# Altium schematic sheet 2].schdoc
size 368 x 260 mm
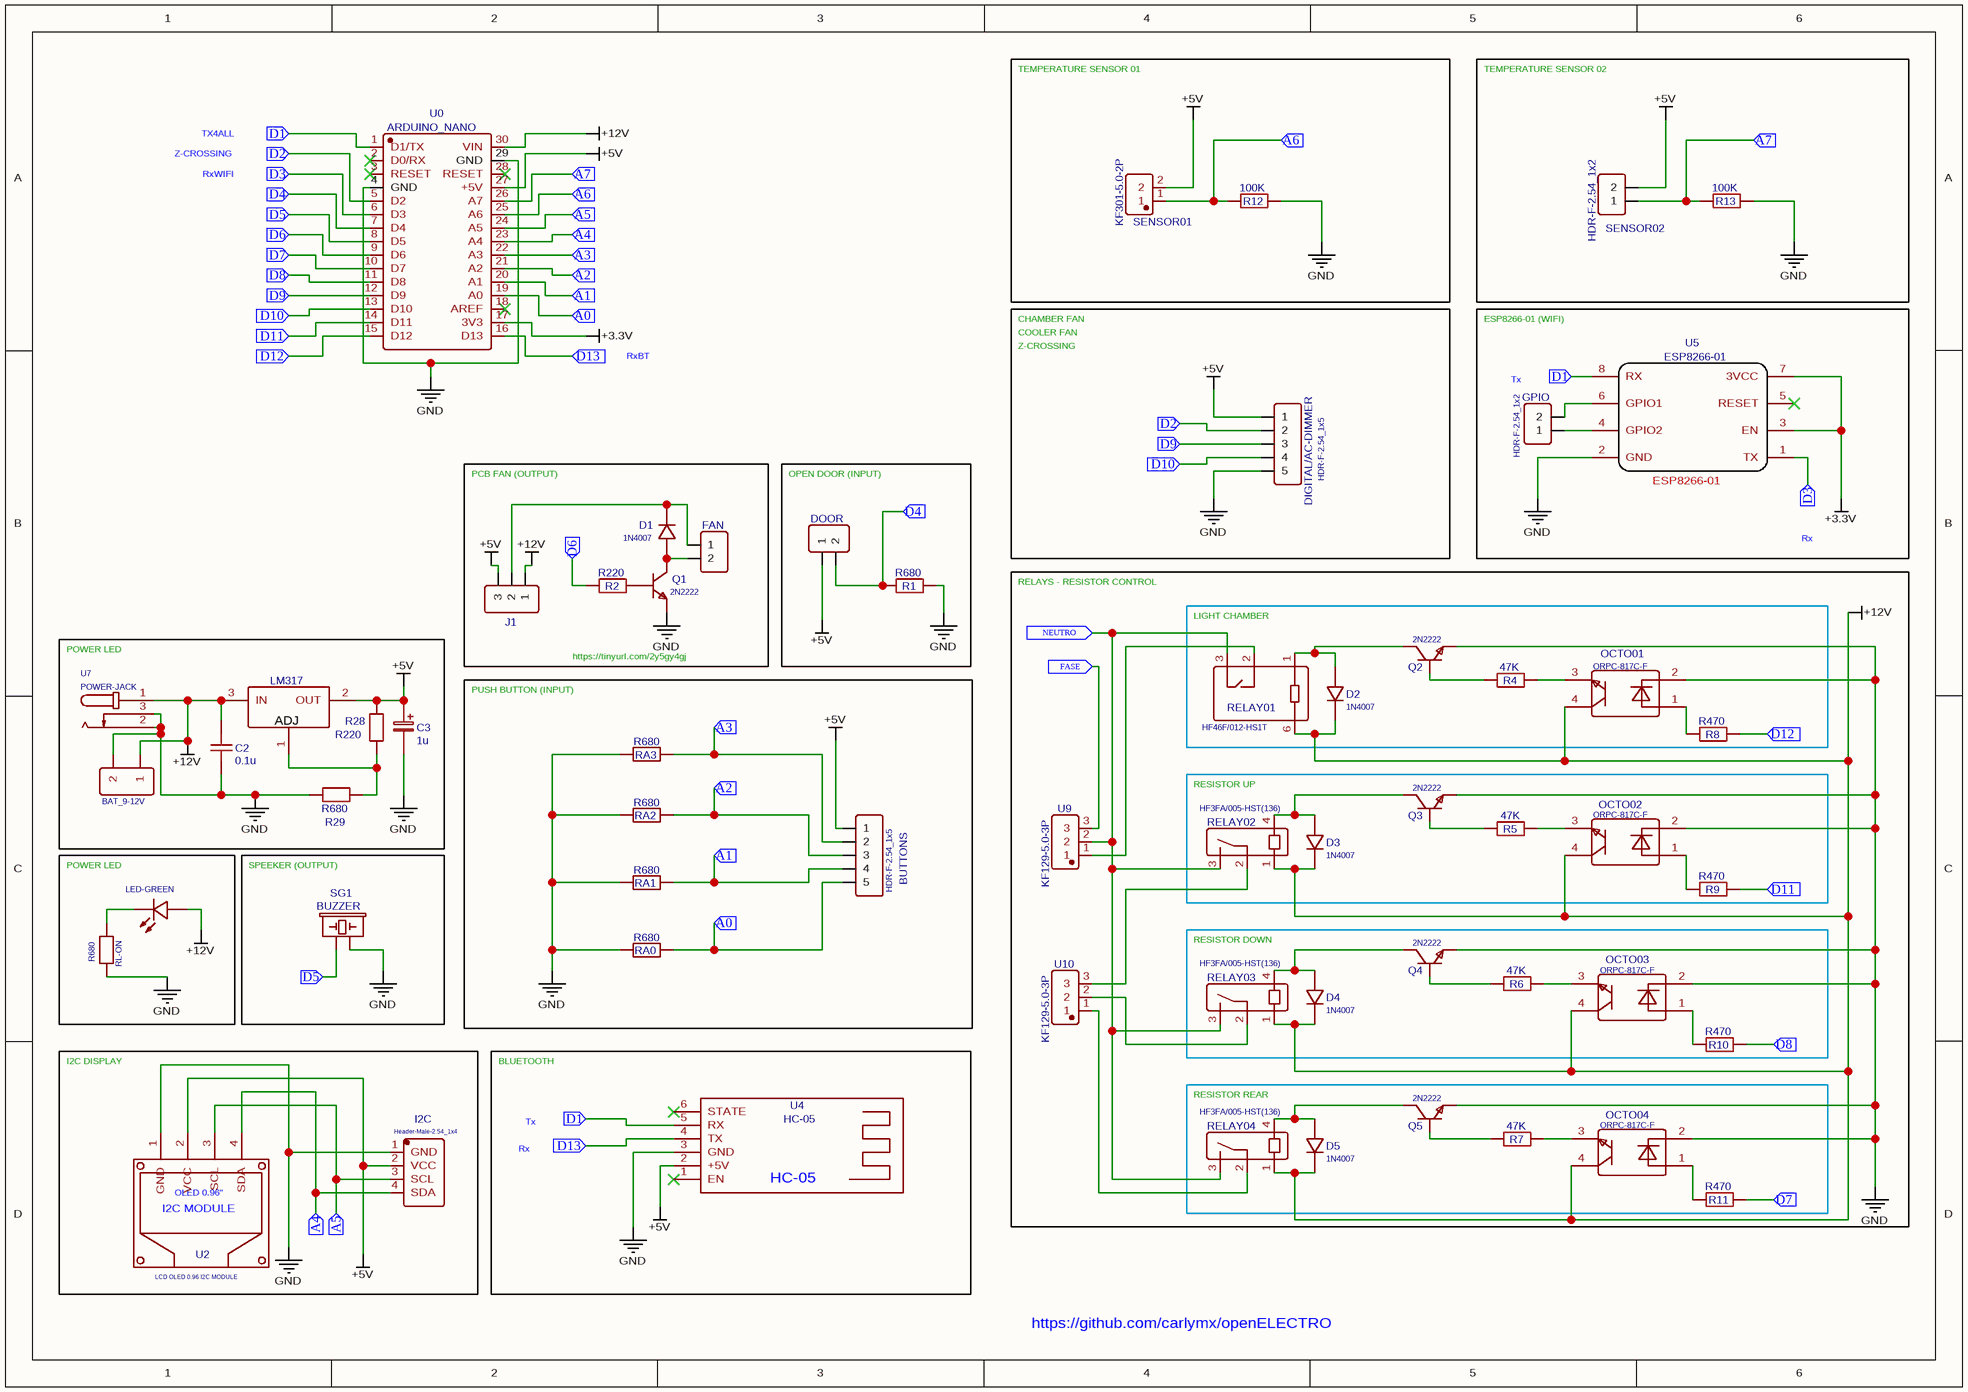
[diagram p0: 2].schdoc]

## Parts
BAT_9-12V  Header-Male-2.54_1x2  [HDR-2X1/2.54]  (value not drawn)
BUTTONS  HDR-F-2.54_1x5  [HDR-F-2.54_1X5]
C2  0.1u  [RAD-0.1]
C3  1u  [CAP-D5.0-F2.0]
D1  1N4007  [DO-41_BD2.4-L4.7-P8.70-D0.6-RD]
D2  1N4007  [DO-41_BD2.4-L4.7-P8.70-D0.9-RD]
D3  1N4007  [DO-41_BD2.4-L4.7-P8.70-D0.9-RD]
D4  1N4007  [DO-41_BD2.4-L4.7-P8.70-D0.9-RD]
D5  1N4007  [DO-41_BD2.4-L4.7-P8.70-D0.9-RD]
DIGITAL/AC-DIMMER  HDR-F-2.54_1x5  [HDR-F-2.54_1X5]
DOOR  HDR-F-2.54_1x2  [HDR-F-2.54_1X2]  (value not drawn)
FAN  HDR-F-2.54_1x2  [HDR-F-2.54_1X2]  (value not drawn)
GPIO  HDR-F-2.54_1x2  [HDR-F-2.54_1X2]
I2C  Header-Male-2.54_1x4  [DIP-1X4P-2.54MM-M]
J1  HDR-F-2.54_1x3  [HDR-F-2.54_1X3]  (value not drawn)
LED-GREEN  204-10SURD/S530-A3  [LED-3MM/2.54]  (value not drawn)
LM317  LM317LZ  [TO-92-3_L4.9-W3.7-P1.27-L]  (value not drawn)
OCTO01  ORPC-817C-F  [DIP-4_L4.6-W6.5-P2.54-LS7.6-BR]
OCTO02  ORPC-817C-F  [DIP-4_L4.6-W6.5-P2.54-LS7.6-BR]
OCTO03  ORPC-817C-F  [DIP-4_L4.6-W6.5-P2.54-LS7.6-BR]
OCTO04  ORPC-817C-F  [DIP-4_L4.6-W6.5-P2.54-LS7.6-BR]
Q1  2N2222  [TO-92-3_L4.9-W3.7-P1.27-L]
Q2  2N2222  [TO-92-3_L4.9-W3.7-P1.27-L]
Q3  2N2222  [TO-92-3_L4.9-W3.7-P1.27-L]
Q4  2N2222  [TO-92-3_L4.9-W3.7-P1.27-L]
Q5  2N2222  [TO-92-3_L4.9-W3.7-P1.27-L]
R1  R680  [R_AXIAL-0.3]
R2  R220  [R_AXIAL-0.3]
R4  47K  [R_AXIAL-0.3]
R5  47K  [R_AXIAL-0.3]
R6  47K  [R_AXIAL-0.3]
R7  47K  [R_AXIAL-0.3]
R8  R470  [R_AXIAL-0.3]
R9  R470  [R_AXIAL-0.3]
R10  R470  [R_AXIAL-0.3]
R11  R470  [R_AXIAL-0.3]
R12  100K  [R_AXIAL-0.3]
R13  100K  [R_AXIAL-0.3]
R28  R220  [R_AXIAL-0.3]
R29  R680  [R_AXIAL-0.3]
RA0  R680  [R_AXIAL-0.3]
RA1  R680  [R_AXIAL-0.3]
RA2  R680  [R_AXIAL-0.3]
RA3  R680  [R_AXIAL-0.3]
RELAY01  HF46F/012-HS1T  [RELAYS-TH_HF46F-XX-HS1-XXX]
RELAY02  HF3FA/005-HST(136)  [RELAY-TH_HF3FA-005-HST-136]
RELAY03  HF3FA/005-HST(136)  [RELAY-TH_HF3FA-005-HST-136]
RELAY04  HF3FA/005-HST(136)  [RELAY-TH_HF3FA-005-HST-136]
RL-ON  R680  [AXIAL-0.3]
SENSOR01  KF301-5.0-2P  [CONN-TH_P5.00_KF301-5.0-2P]
SENSOR02  HDR-F-2.54_1x2  [HDR-F-2.54_1X2]
SG1  BUZZER  [BUZZER-12MM-NS-KIT]
U0  ARDUINO_NANO  [COMM-TH_ARDUINO_NANO]
U2  LCD OLED 0.96 I2C MODULE  [HDR-F-2.54_1X4]
U4  HC-05  [HDR-F-2.54_1X6]
U5  ESP8266-01  [HDR-F-2.54_2X4]
U7  POWER-JACK  [DC-IN-TH_POWER-JACK]
U9  KF129-5.0-3P  [CONN-TH_3P-P5.00_KF129-5.0-3P]
U10  KF129-5.0-3P  [CONN-TH_3P-P5.00_KF129-5.0-3P]

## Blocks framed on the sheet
TEMPERATURE SENSOR 01: R12 SENSOR01
TEMPERATURE SENSOR 02: R13 SENSOR02
OPEN DOOR (INPUT): DOOR R1
RELAYS - RESISTOR CONTROL: U9 U10
POWER LED: BAT_9-12V C2 C3 LM317 R28 R29 U7
LIGHT CHAMBER: D2 OCTO01 Q2 R4 R8 RELAY01
RESISTOR UP: D3 OCTO02 Q3 R5 R9 RELAY02
POWER LED: LED-GREEN RL-ON
SPEEKER (OUTPUT): SG1
RESISTOR DOWN: D4 OCTO03 Q4 R6 R10 RELAY03
I2C DISPLAY: I2C U2
RESISTOR REAR: D5 OCTO04 Q5 R7 R11 RELAY04

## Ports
A0 (in), A1 (in), A2 (in), A3 (in), A4 (in), A5 (in), A6 (in), A7 (in), D1 (in), D2 (in), D3 (in), D4 (in), D5 (in), D6 (in), D7 (in), D8 (in), D9 (in), D10 (in), D11 (in), D12 (in), D13 (in), FASE (in), NEUTRO (in)

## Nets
+3.3V: U0.17(3V3) U5.3(EN) U5.7(3VCC)
+5V: BUTTONS.1 C3.1 DIGITAL/AC-DIMMER.1 DOOR.1 I2C.2(VCC) J1.3 LM317.2(OUT) R28.2 SENSOR01.2 SENSOR02.2 U0.27(+5V) U2.2(VCC) U4.2(+5V)
+12V: BAT_9-12V.1 C2.2 D2.1 D3.1 D4.1 D5.1 J1.1 LED-GREEN.1(A) LM317.3(IN) OCTO01.4 OCTO02.4 OCTO03.4 OCTO04.4 RELAY01.6 RELAY02.1 RELAY03.1 RELAY04.1 U0.30(VIN) U7.1
GND: BAT_9-12V.2 C2.1 C3.2 DIGITAL/AC-DIMMER.5 I2C.1(GND) OCTO01.2 OCTO02.2 OCTO03.2 OCTO04.2 Q1.1(E) Q2.1(E) Q3.1(E) Q4.1(E) Q5.1(E) R1.1 R12.2 R13.2 R29.1 RA0.1 RA1.1 RA2.1 RA3.1 RL-ON.1 SG1.- U0.4(GND) U0.29(GND) U2.1(GND) U4.3(GND) U5.2(GND) U7.2 U7.3
A0: BUTTONS.5 RA0.2 U0.19(A0) ; port A0
A1: BUTTONS.4 RA1.2 U0.20(A1) ; port A1
A2: BUTTONS.3 RA2.2 U0.21(A2) ; port A2
A3: BUTTONS.2 RA3.2 U0.22(A3) ; port A3
A4: I2C.4(SDA) U0.23(A4) U2.4(SDA) ; port A4
A5: I2C.3(SCL) U0.24(A5) U2.3(SCL) ; port A5
A6: R12.1 SENSOR01.1 U0.25(A6) ; port A6
A7: R13.1 SENSOR02.1 U0.26(A7) ; port A7
D1: U0.1(D1/TX) U4.5(RX) U5.8(RX) ; port D1
D2: DIGITAL/AC-DIMMER.2 U0.5(D2) ; port D2
D3: U0.6(D3) U5.1(TX) ; port D3
D4: DOOR.2 R1.2 U0.7(D4) ; port D4
D5: SG1.+ U0.8(D5) ; port D5
D6: R2.1 U0.9(D6) ; port D6
D7: R11.2 U0.10(D7) ; port D7
D8: R10.2 U0.11(D8) ; port D8
D9: DIGITAL/AC-DIMMER.3 U0.12(D9) ; port D9
D10: DIGITAL/AC-DIMMER.4 U0.13(D10) ; port D10
D11: R9.2 U0.14(D11) ; port D11
D12: R8.2 U0.15(D12) ; port D12
D13: U0.16(D13) U4.4(TX) ; port D13
FASE: U9.3 ; port FASE
NEUTRO: RELAY01.3 RELAY02.3 RELAY03.3 RELAY04.3 U9.2 ; port NEUTRO
NetD1_1: D1.1 FAN.1 J1.2
NetD1_2: D1.2 FAN.2 Q1.3(C)
NetD2_2: D2.2 Q2.3(C) RELAY01.1
NetD3_2: D3.2 Q3.3(C) RELAY02.4
NetD4_2: D4.2 Q4.3(C) RELAY03.4
NetD5_2: D5.2 Q5.3(C) RELAY04.4
NetGPIO_1: GPIO.1 U5.4(GPIO2)
NetGPIO_2: GPIO.2 U5.6(GPIO1)
NetLED-GREEN_2: LED-GREEN.2(K) RL-ON.2
NetLM317_1: LM317.1(ADJ) R28.1 R29.2
NetOCTO01_1: OCTO01.1 R8.1
NetOCTO01_3: OCTO01.3 R4.1
NetOCTO02_1: OCTO02.1 R9.1
NetOCTO02_3: OCTO02.3 R5.2
NetOCTO03_1: OCTO03.1 R10.1
NetOCTO03_3: OCTO03.3 R6.2
NetOCTO04_1: OCTO04.1 R11.1
NetOCTO04_3: OCTO04.3 R7.2
NetQ1_2: Q1.2(B) R2.2
NetQ2_2: Q2.2(B) R4.2
NetQ3_2: Q3.2(B) R5.1
NetQ4_2: Q4.2(B) R6.1
NetQ5_2: Q5.2(B) R7.1
NetRELAY01_2: RELAY01.2 U9.1
NetRELAY02_2: RELAY02.2 U10.3
NetRELAY03_2: RELAY03.2 U10.2
NetRELAY04_2: RELAY04.2 U10.1

Not connected (* = marked no-connect by the designer): U0 2(D0/RX)* 3(RESET)* 18(AREF)* 28(RESET)*; U4 1(EN)* 6(STATE)*; U5 5(RESET)*

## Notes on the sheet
- Z-CROSSING
- TX4ALL
- RxWIFI
- COOLER FAN
- CHAMBER FAN
- ESP8266-01 (WIFI)
- RxBT
- (near GPIO) Tx
- PCB FAN (OUTPUT)
- Rx
- https://tinyurl.com/2y5gy4gj
- PUSH BUTTON (INPUT)
- BLUETOOTH
- Tx
- https://github.com/carlymx/openELECTRO

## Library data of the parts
BAT_9-12V = Header-Male-2.54_1x2: BOM_Manufacturer: TE Connectivity; BOM_Manufacturer Part: 826629-2
BUTTONS DIGITAL/AC-DIMMER = HDR-F-2.54_1x5: Contributor: LCEDA_Lib
C2 = 0.1u: nameAlias: Value(F); Contributor: LCEDA_Lib
C3 = 1u: nameAlias: Value(F); Contributor: LCEDA_Lib
D1-D5 = 1N4007: BOM_Manufacturer: SEMTECH; Contributor: LCEDA_Lib
DOOR FAN GPIO SENSOR02 = HDR-F-2.54_1x2: Contributor: LCEDA_Lib
I2C = Header-Male-2.54_1x4: BOM_Manufacturer: Ckmtw; BOM_Manufacturer Part: 210S-1*4P L=11.6MMGold-plated black; Contributor: LCSC
J1 = HDR-F-2.54_1x3: Contributor: LCEDA_Lib
LED-GREEN = 204-10SURD/S530-A3: BOM_Manufacturer: EVERLIGHT
LM317 = LM317LZ: BOM_Manufacturer: ON Semiconductor; BOM_Manufacturer Part: LM317LZG; Contributor: LCSC
OCTO01 OCTO02 OCTO03 OCTO04 = ORPC-817C-F: BOM_Manufacturer: Orient(奥伦德); Contributor: LCSC
Q1-Q5 = 2N2222: BOM_Manufacturer: SEMTECH; Contributor: LCSC
R1 R29 = R680: nameAlias: Value(Ω); Contributor: LCEDA_Lib
R2 R28 = R220: nameAlias: Value(Ω); Contributor: LCEDA_Lib
R4-R7 = 47K: nameAlias: Value(Ω); Contributor: LCEDA_Lib
R8-R11 = R470: nameAlias: Value(Ω); Contributor: LCEDA_Lib
R12 R13 = 100K: nameAlias: Value(Ω); Contributor: LCEDA_Lib
RA0-RA3 RL-ON = R680: nameAlias: Value(Ω)
RELAY01 = HF46F/012-HS1T: BOM_Manufacturer: HF(宏发); Contributor: LCSC
RELAY02 RELAY03 RELAY04 = HF3FA/005-HST(136): BOM_Manufacturer: HF(Xiamen Hongfa Electroacoustic); Contributor: LCSC
SENSOR01 = KF301-5.0-2P: BOM_Manufacturer: Cixi Kefa Elec; Contributor: LCSC
SG1 = BUZZER: Contributor: SparkFun
U0 = ARDUINO_NANO: BOM_Manufacturer: null; Contributor: lcsc
U2 = LCD OLED 0.96 I2C MODULE: BOM_Manufacturer Part: Control Chip SSD1306; Contributor: carlymx
U4 = HC-05: Contributor: SRY TIS
U5 = ESP8266-01: Contributor: Dan3D_Concept
U7 = POWER-JACK: BOM_Manufacturer: null; Contributor: LCSC
U9 U10 = KF129-5.0-3P: BOM_Manufacturer: Cixi Kefa Elec; Contributor: LCSC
